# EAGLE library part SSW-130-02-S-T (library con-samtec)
THROUGH-HOLE .025" SQ POST SOCKET Source: Samtec SSW.pdf
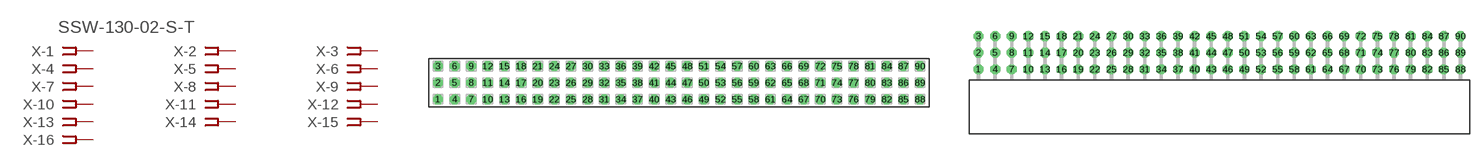
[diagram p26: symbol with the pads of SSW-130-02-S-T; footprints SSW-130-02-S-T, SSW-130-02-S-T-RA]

Designator prefix X; gates -1=FPINV -2=FPIN -3=FPIN -4=FPIN -5=FPIN -6=FPIN -7=FPIN -8=FPIN -9=FPIN -10=FPIN -11=FPIN -12=FPIN -13=FPIN -14=FPIN -15=FPIN -16=FPIN -17=FPIN -18=FPIN -19=FPIN -20=FPIN -21=FPIN -22=FPIN -23=FPIN -24=FPIN -25=FPIN -26=FPIN -27=FPIN -28=FPIN -29=FPIN -30=FPIN -31=FPIN -32=FPIN -33=FPIN -34=FPIN -35=FPIN -36=FPIN -37=FPIN -38=FPIN -39=FPIN -40=FPIN -41=FPIN -42=FPIN -43=FPIN -44=FPIN -45=FPIN -46=FPIN -47=FPIN -48=FPIN -49=FPIN -50=FPIN -51=FPIN -52=FPIN -53=FPIN -54=FPIN -55=FPIN -56=FPIN -57=FPIN -58=FPIN -59=FPIN -60=FPIN -61=FPIN -62=FPIN -63=FPIN -64=FPIN -65=FPIN -66=FPIN -67=FPIN -68=FPIN -69=FPIN -70=FPIN -71=FPIN -72=FPIN -73=FPIN -74=FPIN -75=FPIN -76=FPIN -77=FPIN -78=FPIN -79=FPIN -80=FPIN -81=FPIN -82=FPIN -83=FPIN -84=FPIN -85=FPIN -86=FPIN -87=FPIN -88=FPIN -89=FPIN -90=FPIN

## SSW-130-02-S-T (MPN: SSW-130-02-S-T; OC_FARNELL: unknown; OC_NEWARK: 83P0026)  [SSW-130-02-S-T]
1  -1:1  pas
2  -2:1  pas
3  -3:1  pas
4  -4:1  pas
5  -5:1  pas
6  -6:1  pas
7  -7:1  pas
8  -8:1  pas
9  -9:1  pas
10  -10:1  pas
11  -11:1  pas
12  -12:1  pas
13  -13:1  pas
14  -14:1  pas
15  -15:1  pas
16  -16:1  pas
17  -17:1  pas
18  -18:1  pas
19  -19:1  pas
20  -20:1  pas
21  -21:1  pas
22  -22:1  pas
23  -23:1  pas
24  -24:1  pas
25  -25:1  pas
26  -26:1  pas
27  -27:1  pas
28  -28:1  pas
29  -29:1  pas
30  -30:1  pas
31  -31:1  pas
32  -32:1  pas
33  -33:1  pas
34  -34:1  pas
35  -35:1  pas
36  -36:1  pas
37  -37:1  pas
38  -38:1  pas
39  -39:1  pas
40  -40:1  pas
41  -41:1  pas
42  -42:1  pas
43  -43:1  pas
44  -44:1  pas
45  -45:1  pas
46  -46:1  pas
47  -47:1  pas
48  -48:1  pas
49  -49:1  pas
50  -50:1  pas
51  -51:1  pas
52  -52:1  pas
53  -53:1  pas
54  -54:1  pas
55  -55:1  pas
56  -56:1  pas
57  -57:1  pas
58  -58:1  pas
59  -59:1  pas
60  -60:1  pas
61  -61:1  pas
62  -62:1  pas
63  -63:1  pas
64  -64:1  pas
65  -65:1  pas
66  -66:1  pas
67  -67:1  pas
68  -68:1  pas
69  -69:1  pas
70  -70:1  pas
71  -71:1  pas
72  -72:1  pas
73  -73:1  pas
74  -74:1  pas
75  -75:1  pas
76  -76:1  pas
77  -77:1  pas
78  -78:1  pas
79  -79:1  pas
80  -80:1  pas
81  -81:1  pas
82  -82:1  pas
83  -83:1  pas
84  -84:1  pas
85  -85:1  pas
86  -86:1  pas
87  -87:1  pas
88  -88:1  pas
89  -89:1  pas
90  -90:1  pas

## SSW-130-02-S-TRA (MPN: SSW-130-02-S-T-RA; OC_FARNELL: unknown; OC_NEWARK: 83P0027)  [SSW-130-02-S-T-RA]
Pads as for SSW-130-02-S-T

## Footprint SSW-130-02-S-T (pad centres in mm)
THROUGH-HOLE .025" SQ POST SOCKET Source: Samtec SSW.pdf
drill 1 pad 1.5 octagon: 1 -36.83,-2.54; 2 -36.83,0; 3 -36.83,2.54; 4 -34.29,-2.54; 5 -34.29,0; 6 -34.29,2.54; 7 -31.75,-2.54; 8 -31.75,0; 9 -31.75,2.54; 10 -29.21,-2.54; 11 -29.21,0; 12 -29.21,2.54; 13 -26.67,-2.54; 14 -26.67,0; 15 -26.67,2.54; 16 -24.13,-2.54; 17 -24.13,0; 18 -24.13,2.54; 19 -21.59,-2.54; 20 -21.59,0; 21 -21.59,2.54; 22 -19.05,-2.54; 23 -19.05,0; 24 -19.05,2.54; 25 -16.51,-2.54; 26 -16.51,0; 27 -16.51,2.54; 28 -13.97,-2.54; 29 -13.97,0; 30 -13.97,2.54; 31 -11.43,-2.54; 32 -11.43,0; 33 -11.43,2.54; 34 -8.89,-2.54; 35 -8.89,0; 36 -8.89,2.54; 37 -6.35,-2.54; 38 -6.35,0; 39 -6.35,2.54; 40 -3.81,-2.54; 41 -3.81,0; 42 -3.81,2.54; 43 -1.27,-2.54; 44 -1.27,0; 45 -1.27,2.54; 46 1.27,-2.54; 47 1.27,0; 48 1.27,2.54; 49 3.81,-2.54; 50 3.81,0; 51 3.81,2.54; 52 6.35,-2.54; 53 6.35,0; 54 6.35,2.54; 55 8.89,-2.54; 56 8.89,0; 57 8.89,2.54; 58 11.43,-2.54; 59 11.43,0; 60 11.43,2.54; 61 13.97,-2.54; 62 13.97,0; 63 13.97,2.54; 64 16.51,-2.54; 65 16.51,0; 66 16.51,2.54; 67 19.05,-2.54; 68 19.05,0; 69 19.05,2.54; 70 21.59,-2.54; 71 21.59,0; 72 21.59,2.54; 73 24.13,-2.54; 74 24.13,0; 75 24.13,2.54; 76 26.67,-2.54; 77 26.67,0; 78 26.67,2.54; 79 29.21,-2.54; 80 29.21,0; 81 29.21,2.54; 82 31.75,-2.54; 83 31.75,0; 84 31.75,2.54; 85 34.29,-2.54; 86 34.29,0; 87 34.29,2.54; 88 36.83,-2.54; 89 36.83,0; 90 36.83,2.54

## Footprint SSW-130-02-S-T-RA (pad centres in mm)
THROUGH-HOLE .025" SQ POST SOCKET Source: Samtec SSW.pdf
drill 1 pad 1.5 octagon: 1 -36.83,1.524; 2 -36.83,4.064; 3 -36.83,6.604; 4 -34.29,1.524; 5 -34.29,4.064; 6 -34.29,6.604; 7 -31.75,1.524; 8 -31.75,4.064; 9 -31.75,6.604; 10 -29.21,1.524; 11 -29.21,4.064; 12 -29.21,6.604; 13 -26.67,1.524; 14 -26.67,4.064; 15 -26.67,6.604; 16 -24.13,1.524; 17 -24.13,4.064; 18 -24.13,6.604; 19 -21.59,1.524; 20 -21.59,4.064; 21 -21.59,6.604; 22 -19.05,1.524; 23 -19.05,4.064; 24 -19.05,6.604; 25 -16.51,1.524; 26 -16.51,4.064; 27 -16.51,6.604; 28 -13.97,1.524; 29 -13.97,4.064; 30 -13.97,6.604; 31 -11.43,1.524; 32 -11.43,4.064; 33 -11.43,6.604; 34 -8.89,1.524; 35 -8.89,4.064; 36 -8.89,6.604; 37 -6.35,1.524; 38 -6.35,4.064; 39 -6.35,6.604; 40 -3.81,1.524; 41 -3.81,4.064; 42 -3.81,6.604; 43 -1.27,1.524; 44 -1.27,4.064; 45 -1.27,6.604; 46 1.27,1.524; 47 1.27,4.064; 48 1.27,6.604; 49 3.81,1.524; 50 3.81,4.064; 51 3.81,6.604; 52 6.35,1.524; 53 6.35,4.064; 54 6.35,6.604; 55 8.89,1.524; 56 8.89,4.064; 57 8.89,6.604; 58 11.43,1.524; 59 11.43,4.064; 60 11.43,6.604; 61 13.97,1.524; 62 13.97,4.064; 63 13.97,6.604; 64 16.51,1.524; 65 16.51,4.064; 66 16.51,6.604; 67 19.05,1.524; 68 19.05,4.064; 69 19.05,6.604; 70 21.59,1.524; 71 21.59,4.064; 72 21.59,6.604; 73 24.13,1.524; 74 24.13,4.064; 75 24.13,6.604; 76 26.67,1.524; 77 26.67,4.064; 78 26.67,6.604; 79 29.21,1.524; 80 29.21,4.064; 81 29.21,6.604; 82 31.75,1.524; 83 31.75,4.064; 84 31.75,6.604; 85 34.29,1.524; 86 34.29,4.064; 87 34.29,6.604; 88 36.83,1.524; 89 36.83,4.064; 90 36.83,6.604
